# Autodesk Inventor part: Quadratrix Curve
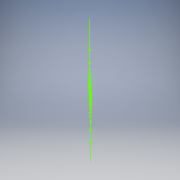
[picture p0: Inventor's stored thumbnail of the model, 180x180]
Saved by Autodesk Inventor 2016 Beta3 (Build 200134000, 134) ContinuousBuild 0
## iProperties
Created: 2008-02
Part Number: Quadratrix Curve
Document SubType Name: Modeling
Designer: Autodesk, Inc.
Density: 1 g/cm^3
Material: Generic
Appearance: Default
Author: Autodesk, Inc.
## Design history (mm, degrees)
sketch "Sketch1"
  geometry: 298 further points
  constraints: 298 other
